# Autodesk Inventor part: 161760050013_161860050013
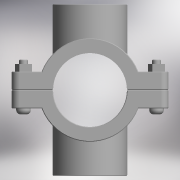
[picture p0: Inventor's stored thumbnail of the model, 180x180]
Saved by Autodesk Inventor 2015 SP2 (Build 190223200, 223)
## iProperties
Created: 2017-05
Part Number: 161760050013_161860050013
Material: Generic
Description: PLASSON DOUBLE SADDLE 50-1.1/4"
Document SubType Name: Modeling
Designer: KIM
Density: 1 g/cm^3
Appearance: Default
Author: KIM
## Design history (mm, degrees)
derived "16176.ipt"
feature "Solid1::16176.ipt"
feature "Solid2::16176.ipt"
tag "TaggingFeature1"
body "Solid1"
body "Solid2"
other parameters: "d1" = 106, "d2" = 25, "d4" = 73, "d5" = 0, "d6" = 5.3, "d7" = 106, "d8" = 0.1, "d10" = 0, "d11" = 0.5, "d20" = 0.5, "d23" = 0.5, "d37" = 8, "d38" = 33, "d39" = 0, "d40" = 3, "d41" = 5, "d42" = 0, "d43" = 6, "d44" = 3, "d45" = 0, "d46" = 0.5, "d52" = 38.952, "d53" = 25, "d54" = 0, "d55" = 25, "d57" = 0, "d58" = 54, "d60" = 0, "d63" = 36.5, "d66" = 0, "d67" = 116, "d68" = 50.6376, "d69" = 38.952, "d70" = 25, "d71" = 0, "d72" = 25, "d74" = 0, "d75" = 0.5, "B_" = 25, "G_" = 38.952, "A_" = 58, "L_" = 106, "L_1" = 73, "l_2" = 25
